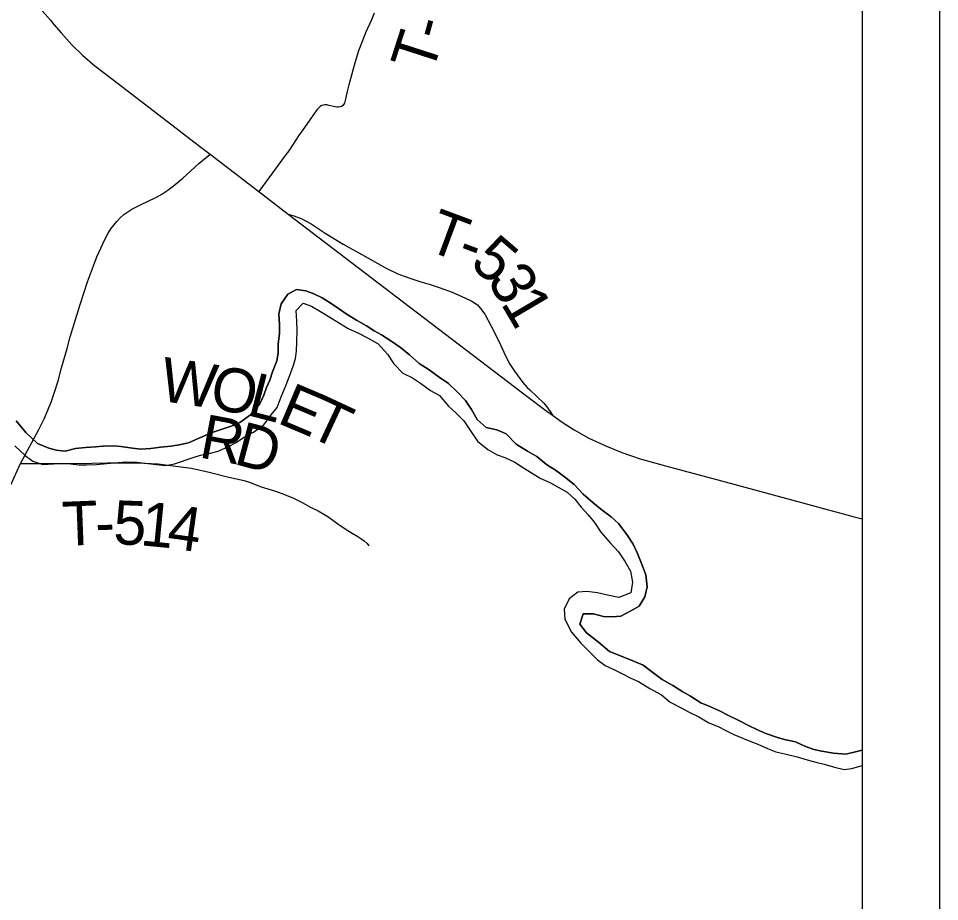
# Model space of a CAD drawing. Extents: x 0 to 34, y 0 to 22.
# Drawn here: x 7.688 to 8.876, y 17.181 to 18.32 of the extents above; entities that cross this region are included whole.
import ezdxf

# ---------------------------------------------------------------- set-up
doc = ezdxf.new("R2010")
doc.units = 0
for name, color, linetype in [('GM_X_County_Road', 7, 'Continuous'), ('GM_X_Major_River', 7, 'Continuous'), ('GM_X_Township_Road', 7, 'Continuous'), ('GM_X_Township_Road_Text', 7, 'Continuous'), ('SH_Data', 7, 'Continuous')]:
    doc.layers.add(name, color=color, linetype=linetype)

msp = doc.modelspace()

# ---------------------------------------------------------------- linework, layer by layer
at = {"layer": 'GM_X_County_Road'}
for points in [[(7.6607, 18.396), (7.6784, 18.3758), (7.6923, 18.3599), (7.7022, 18.3484), (7.7147, 18.334), (7.7289, 18.318), (7.7335, 18.3126)], [(7.7335, 18.3126), (7.7429, 18.3019), (7.7566, 18.2863), (7.7705, 18.273), (7.7864, 18.2592), (7.8093, 18.2414), (7.8799, 18.1872), (7.9195, 18.157), (7.9349, 18.1452), (7.9977, 18.0969), (8.0358, 18.0678), (8.201, 17.942), (8.347, 17.8304), (8.3664, 17.8156), (8.3766, 17.8083), (8.3892, 17.7994), (8.4049, 17.7895), (8.4239, 17.779), (8.4463, 17.7684), (8.4664, 17.7602), (8.4899, 17.7522), (8.5227, 17.7429), (8.5949, 17.7238), (8.7028, 17.6944), (8.7659, 17.6775), (8.7763, 17.6747)], [(7.7504, 17.8946), (7.7546, 17.9096), (7.7672, 17.9512), (7.7769, 17.9806), (7.7843, 18.0011), (7.789, 18.0126), (7.7964, 18.0295), (7.8005, 18.0379), (7.8035, 18.0434), (7.8069, 18.0487), (7.8106, 18.0537), (7.8146, 18.0585), (7.8189, 18.0631), (7.8236, 18.0672), (7.8287, 18.071), (7.8341, 18.0742), (7.8452, 18.0799), (7.8648, 18.0891), (7.8729, 18.0935), (7.8806, 18.0986), (7.8879, 18.1042), (7.8996, 18.1143), (7.9203, 18.133), (7.9298, 18.141), (7.9349, 18.1452)], [(7.6778, 17.7185), (7.6905, 17.7463), (7.7139, 17.7898), (7.7207, 17.8036), (7.7258, 17.8149), (7.7303, 17.8264), (7.7343, 17.8381), (7.7388, 17.8529), (7.7434, 17.8694), (7.7504, 17.8946)]]:
    msp.add_lwpolyline(points, dxfattribs=at)
at = {"layer": 'GM_X_Major_River'}
for p, q in [((8.0353, 17.9645), (8.0267, 17.9523)), ((8.0466, 17.9707), (8.0353, 17.9645)), ((8.0587, 17.9689), (8.0466, 17.9707)), ((8.0689, 17.9649), (8.0587, 17.9689)), ((8.0796, 17.96), (8.0689, 17.9649)), ((8.0267, 17.9523), (8.0238, 17.9394)), ((8.046, 17.9434), (8.055, 17.953)), ((8.055, 17.953), (8.0657, 17.9493)), ((8.0657, 17.9493), (8.0794, 17.9411)), ((8.0898, 17.9533), (8.0796, 17.96)), ((8.102, 17.9451), (8.0898, 17.9533)), ((8.0238, 17.9394), (8.0246, 17.925)), ((8.0469, 17.9298), (8.046, 17.9434)), ((8.0794, 17.9411), (8.0896, 17.9347)), ((8.1119, 17.9383), (8.102, 17.9451)), ((8.1237, 17.9309), (8.1119, 17.9383)), ((8.0474, 17.9173), (8.0469, 17.9298)), ((8.0896, 17.9347), (8.1018, 17.9273)), ((8.1018, 17.9273), (8.1132, 17.9202)), ((8.137, 17.9238), (8.1237, 17.9309)), ((8.0247, 17.9144), (8.023, 17.9)), ((8.0246, 17.925), (8.0247, 17.9144)), ((8.0468, 17.9036), (8.0474, 17.9173)), ((8.1132, 17.9202), (8.1265, 17.9142)), ((8.1265, 17.9142), (8.1391, 17.9079)), ((8.1465, 17.9171), (8.137, 17.9238)), ((8.156, 17.9122), (8.1465, 17.9171)), ((8.0465, 17.8911), (8.0468, 17.9036)), ((8.1391, 17.9079), (8.152, 17.9004)), ((8.1671, 17.9051), (8.156, 17.9122)), ((8.1808, 17.8958), (8.1671, 17.9051)), ((8.023, 17.9), (8.0227, 17.8883)), ((8.0451, 17.8816), (8.0465, 17.8911)), ((8.152, 17.9004), (8.1638, 17.8873)), ((8.1922, 17.8864), (8.1808, 17.8958)), ((8.0209, 17.8784), (8.0157, 17.8643)), ((8.0227, 17.8883), (8.0209, 17.8784)), ((8.0421, 17.8718), (8.0451, 17.8816)), ((8.1638, 17.8873), (8.1719, 17.8745)), ((8.2048, 17.8751), (8.1922, 17.8864)), ((8.0373, 17.8588), (8.0421, 17.8718)), ((8.1719, 17.8745), (8.1837, 17.8628)), ((8.2177, 17.8669), (8.2048, 17.8751)), ((8.2307, 17.8576), (8.2177, 17.8669)), ((8.0157, 17.8643), (8.012, 17.8537)), ((8.0333, 17.8474), (8.0373, 17.8588)), ((8.1837, 17.8628), (8.1963, 17.8565)), ((8.1963, 17.8565), (8.2065, 17.8498)), ((8.2425, 17.8493), (8.2307, 17.8576)), ((8.0076, 17.8442), (8.0042, 17.8343)), ((8.012, 17.8537), (8.0076, 17.8442)), ((8.0266, 17.8322), (8.0333, 17.8474)), ((8.2065, 17.8498), (8.2195, 17.8404)), ((8.2543, 17.8381), (8.2425, 17.8493)), ((8.0042, 17.8343), (7.999, 17.8229)), ((8.0214, 17.8185), (8.0266, 17.8322)), ((8.2195, 17.8404), (8.2309, 17.8337)), ((8.2309, 17.8337), (8.2427, 17.8202)), ((8.2646, 17.8276), (8.2543, 17.8381)), ((7.999, 17.8229), (7.987, 17.8091)), ((8.0139, 17.809), (8.0214, 17.8185)), ((8.2427, 17.8202), (8.2523, 17.8112)), ((8.2723, 17.8159), (8.2646, 17.8276)), ((7.987, 17.8091), (7.9735, 17.7988)), ((8.0042, 17.796), (8.0139, 17.809)), ((8.2523, 17.8112), (8.2622, 17.801)), ((8.2796, 17.8027), (8.2723, 17.8159)), ((7.6974, 17.786), (7.6848, 17.8011)), ((7.9633, 17.7949), (7.9505, 17.7902)), ((7.9735, 17.7988), (7.9633, 17.7949)), ((7.991, 17.7864), (8.0042, 17.796)), ((8.2622, 17.801), (8.2718, 17.7871)), ((8.2914, 17.7926), (8.2796, 17.8027)), ((7.7123, 17.7721), (7.6974, 17.786)), ((7.9365, 17.7855), (7.9218, 17.7793)), ((7.9505, 17.7902), (7.9365, 17.7855)), ((7.9782, 17.7795), (7.991, 17.7864)), ((8.2718, 17.7871), (8.2802, 17.775)), ((8.305, 17.7897), (8.2914, 17.7926)), ((8.3172, 17.7845), (8.305, 17.7897)), ((8.3298, 17.7709), (8.3172, 17.7845)), ((7.7267, 17.7658), (7.7123, 17.7721)), ((7.9071, 17.7728), (7.8951, 17.7704)), ((7.9218, 17.7793), (7.9071, 17.7728)), ((7.9586, 17.7679), (7.9684, 17.7733)), ((7.9684, 17.7733), (7.9782, 17.7795)), ((8.2802, 17.775), (8.2932, 17.7642)), ((8.3446, 17.762), (8.3298, 17.7709)), ((7.6832, 17.7688), (7.6962, 17.7564)), ((7.7362, 17.7633), (7.7267, 17.7658)), ((7.7479, 17.7622), (7.7362, 17.7633)), ((7.7615, 17.7654), (7.7479, 17.7622)), ((7.7744, 17.7666), (7.7615, 17.7654)), ((7.7872, 17.7675), (7.7744, 17.7666)), ((7.7971, 17.7684), (7.7872, 17.7675)), ((7.8099, 17.7689), (7.7971, 17.7684)), ((7.8198, 17.7682), (7.8099, 17.7689)), ((7.8349, 17.7661), (7.8198, 17.7682)), ((7.8455, 17.7646), (7.8349, 17.7661)), ((7.8584, 17.7655), (7.8455, 17.7646)), ((7.8709, 17.7671), (7.8584, 17.7655)), ((7.8841, 17.7684), (7.8709, 17.7671)), ((7.8951, 17.7704), (7.8841, 17.7684)), ((7.9228, 17.757), (7.9356, 17.7594)), ((7.9356, 17.7594), (7.9455, 17.7621)), ((7.9455, 17.7621), (7.9586, 17.7679)), ((8.2932, 17.7642), (8.3053, 17.7575)), ((8.3564, 17.7553), (8.3446, 17.762)), ((7.6962, 17.7564), (7.7064, 17.7493)), ((7.7064, 17.7493), (7.7193, 17.7449)), ((7.8018, 17.746), (7.8162, 17.7473)), ((7.8162, 17.7473), (7.8264, 17.7482)), ((7.8264, 17.7482), (7.8404, 17.7479)), ((7.8404, 17.7479), (7.8514, 17.7465)), ((7.8892, 17.7457), (7.913, 17.7539)), ((7.913, 17.7539), (7.9228, 17.757)), ((8.3053, 17.7575), (8.3152, 17.7538)), ((8.3152, 17.7538), (8.3281, 17.7478)), ((8.3281, 17.7478), (8.3395, 17.7407)), ((8.369, 17.7448), (8.3564, 17.7553)), ((7.7193, 17.7449), (7.7329, 17.7458)), ((7.7329, 17.7458), (7.7435, 17.7466)), ((7.7435, 17.7466), (7.7549, 17.7456)), ((7.7549, 17.7456), (7.7655, 17.7442)), ((7.7655, 17.7442), (7.7753, 17.7443)), ((7.7753, 17.7443), (7.7886, 17.7448)), ((7.7886, 17.7448), (7.8018, 17.746)), ((7.8514, 17.7465), (7.8654, 17.7447)), ((7.8654, 17.7447), (7.8779, 17.7437)), ((7.8779, 17.7437), (7.8892, 17.7457)), ((8.3395, 17.7407), (8.3608, 17.7273)), ((8.3819, 17.7366), (8.369, 17.7448)), ((8.3922, 17.7291), (8.3819, 17.7366)), ((8.3608, 17.7273), (8.3741, 17.7213)), ((8.4048, 17.7189), (8.3922, 17.7291)), ((8.3741, 17.7213), (8.384, 17.7157)), ((8.384, 17.7157), (8.3958, 17.709)), ((8.4163, 17.7065), (8.4048, 17.7189)), ((8.3958, 17.709), (8.4057, 17.7)), ((8.4057, 17.7), (8.4138, 17.6899)), ((8.4292, 17.6953), (8.4163, 17.7065)), ((8.4138, 17.6899), (8.4229, 17.6797)), ((8.441, 17.6859), (8.4292, 17.6953)), ((8.4229, 17.6797), (8.431, 17.6699)), ((8.4525, 17.6773), (8.441, 17.6859)), ((8.462, 17.6687), (8.4525, 17.6773)), ((8.431, 17.6699), (8.439, 17.6575)), ((8.4727, 17.6544), (8.462, 17.6687)), ((8.439, 17.6575), (8.4512, 17.6436)), ((8.4808, 17.642), (8.4727, 17.6544)), ((8.4512, 17.6436), (8.4619, 17.6323)), ((8.4865, 17.6299), (8.4808, 17.642)), ((8.4619, 17.6323), (8.4704, 17.6191)), ((8.4916, 17.617), (8.4865, 17.6299)), ((8.4704, 17.6191), (8.4773, 17.6071)), ((8.4974, 17.6023), (8.4916, 17.617)), ((8.4773, 17.6071), (8.4801, 17.5931)), ((8.4801, 17.5931), (8.4779, 17.5794)), ((8.499, 17.5872), (8.4974, 17.6023)), ((8.4211, 17.5808), (8.4094, 17.5803)), ((8.4348, 17.5794), (8.4211, 17.5808)), ((8.4961, 17.5743), (8.499, 17.5872)), ((8.3985, 17.5715), (8.3918, 17.5582)), ((8.4094, 17.5803), (8.3985, 17.5715)), ((8.4477, 17.5761), (8.4348, 17.5794)), ((8.4624, 17.5732), (8.4477, 17.5761)), ((8.4779, 17.5794), (8.4624, 17.5732)), ((8.4886, 17.5621), (8.4961, 17.5743)), ((8.3918, 17.5582), (8.3927, 17.5453)), ((8.4781, 17.5559), (8.4886, 17.5621)), ((8.3927, 17.5453), (8.4015, 17.5283)), ((8.412, 17.539), (8.4165, 17.5523)), ((8.4165, 17.5523), (8.4297, 17.5521)), ((8.4297, 17.5521), (8.4426, 17.5488)), ((8.4426, 17.5488), (8.4536, 17.5481)), ((8.4536, 17.5481), (8.4649, 17.549)), ((8.4649, 17.549), (8.4781, 17.5559)), ((8.4208, 17.5277), (8.412, 17.539)), ((8.4015, 17.5283), (8.4134, 17.5144)), ((8.4361, 17.5154), (8.4208, 17.5277)), ((8.4134, 17.5144), (8.4237, 17.5039)), ((8.4502, 17.5037), (8.4361, 17.5154)), ((8.4237, 17.5039), (8.4348, 17.493)), ((8.4711, 17.4956), (8.4502, 17.5037)), ((8.4348, 17.493), (8.4447, 17.4855)), ((8.4447, 17.4855), (8.4576, 17.4796)), ((8.4828, 17.4908), (8.4711, 17.4956)), ((8.4938, 17.486), (8.4828, 17.4908)), ((8.5045, 17.4777), (8.4938, 17.486)), ((8.4576, 17.4796), (8.4678, 17.4743)), ((8.4678, 17.4743), (8.4777, 17.4691)), ((8.5182, 17.4676), (8.5045, 17.4777)), ((8.4777, 17.4691), (8.488, 17.4647)), ((8.488, 17.4647), (8.5024, 17.4557)), ((8.5323, 17.4598), (8.5182, 17.4676)), ((8.5024, 17.4557), (8.5176, 17.4475)), ((8.5452, 17.4516), (8.5323, 17.4598)), ((8.5551, 17.446), (8.5452, 17.4516)), ((8.5176, 17.4475), (8.5287, 17.4381)), ((8.5287, 17.4381), (8.5428, 17.4307)), ((8.5684, 17.4374), (8.5551, 17.446)), ((8.5428, 17.4307), (8.553, 17.4255)), ((8.5798, 17.4325), (8.5684, 17.4374)), ((8.5924, 17.427), (8.5798, 17.4325)), ((8.6041, 17.421), (8.5924, 17.427)), ((8.553, 17.4255), (8.5656, 17.4192)), ((8.5656, 17.4192), (8.5785, 17.4117)), ((8.6182, 17.4143), (8.6041, 17.421)), ((8.6307, 17.4076), (8.6182, 17.4143)), ((8.5785, 17.4117), (8.5906, 17.4069)), ((8.5906, 17.4069), (8.6005, 17.4017)), ((8.6406, 17.4028), (8.6307, 17.4076)), ((8.652, 17.3976), (8.6406, 17.4028)), ((8.6005, 17.4017), (8.6108, 17.3964)), ((8.6108, 17.3964), (8.6305, 17.3883)), ((8.6683, 17.392), (8.652, 17.3976)), ((8.6778, 17.3895), (8.6683, 17.392)), ((8.6305, 17.3883), (8.6419, 17.3842)), ((8.6419, 17.3842), (8.6541, 17.3783)), ((8.6903, 17.3869), (8.6778, 17.3895)), ((8.7025, 17.3814), (8.6903, 17.3869)), ((8.7139, 17.3773), (8.7025, 17.3814)), ((8.6541, 17.3783), (8.6651, 17.3742)), ((8.6651, 17.3742), (8.6768, 17.3717)), ((8.6768, 17.3717), (8.6924, 17.3676)), ((8.6924, 17.3676), (8.7053, 17.364)), ((8.7245, 17.3751), (8.7139, 17.3773)), ((8.7393, 17.3726), (8.7245, 17.3751)), ((8.7552, 17.3712), (8.7393, 17.3726)), ((8.7676, 17.374), (8.7552, 17.3712)), ((8.7763, 17.3763), (8.7676, 17.374)), ((8.7053, 17.364), (8.7167, 17.361)), ((8.7167, 17.361), (8.7273, 17.3581)), ((8.7273, 17.3581), (8.7409, 17.3544)), ((8.7629, 17.3527), (8.7763, 17.3566)), ((8.7409, 17.3544), (8.7531, 17.3515)), ((8.7531, 17.3515), (8.7629, 17.3527))]:
    msp.add_line(p, q, dxfattribs=at)
for points in [[(7.6848, 17.8011), (7.6974, 17.786), (7.7123, 17.7721), (7.7267, 17.7658), (7.7362, 17.7633), (7.7479, 17.7622), (7.7615, 17.7654), (7.7744, 17.7666), (7.7872, 17.7675), (7.7971, 17.7684), (7.8099, 17.7689), (7.8198, 17.7682), (7.8349, 17.7661), (7.8455, 17.7646), (7.8584, 17.7655), (7.8709, 17.7671), (7.8841, 17.7684), (7.8951, 17.7704), (7.9071, 17.7728), (7.9218, 17.7793), (7.9365, 17.7855), (7.9505, 17.7902), (7.9633, 17.7949), (7.9735, 17.7988), (7.987, 17.8091), (7.999, 17.8229), (8.0042, 17.8343), (8.0076, 17.8442), (8.012, 17.8537), (8.0157, 17.8643), (8.0209, 17.8784), (8.0227, 17.8883), (8.023, 17.9), (8.0247, 17.9144), (8.0246, 17.925), (8.0238, 17.9394), (8.0267, 17.9523), (8.0353, 17.9645), (8.0466, 17.9707), (8.0587, 17.9689), (8.0689, 17.9649), (8.0796, 17.96), (8.0898, 17.9533), (8.102, 17.9451), (8.1119, 17.9383), (8.1237, 17.9309), (8.137, 17.9238), (8.1465, 17.9171), (8.156, 17.9122), (8.1671, 17.9051), (8.1808, 17.8958), (8.1922, 17.8864), (8.2048, 17.8751)], [(7.6832, 17.7688), (7.6962, 17.7564), (7.7064, 17.7493), (7.7193, 17.7449), (7.7329, 17.7458), (7.7435, 17.7466), (7.7549, 17.7456), (7.7655, 17.7442), (7.7753, 17.7443), (7.7886, 17.7448), (7.8018, 17.746), (7.8162, 17.7473), (7.8264, 17.7482), (7.8404, 17.7479), (7.8514, 17.7465), (7.8654, 17.7447), (7.8779, 17.7437), (7.8892, 17.7457), (7.913, 17.7539), (7.9228, 17.757), (7.9356, 17.7594), (7.9455, 17.7621), (7.9586, 17.7679), (7.9684, 17.7733), (7.9782, 17.7795), (7.991, 17.7864), (8.0042, 17.796), (8.0139, 17.809), (8.0214, 17.8185), (8.0266, 17.8322), (8.0333, 17.8474), (8.0373, 17.8588), (8.0421, 17.8718), (8.0451, 17.8816), (8.0465, 17.8911), (8.0468, 17.9036), (8.0474, 17.9173), (8.0469, 17.9298), (8.046, 17.9434), (8.055, 17.953), (8.0657, 17.9493), (8.0794, 17.9411), (8.0896, 17.9347), (8.1018, 17.9273), (8.1132, 17.9202), (8.1265, 17.9142), (8.1391, 17.9079), (8.152, 17.9004), (8.1638, 17.8873), (8.1719, 17.8745), (8.1837, 17.8628), (8.1963, 17.8565), (8.2065, 17.8498), (8.2195, 17.8404)], [(8.2048, 17.8751), (8.2177, 17.8669), (8.2307, 17.8576), (8.2425, 17.8493), (8.2543, 17.8381), (8.2646, 17.8276), (8.2723, 17.8159), (8.2796, 17.8027), (8.2914, 17.7926), (8.305, 17.7897), (8.3172, 17.7845), (8.3298, 17.7709), (8.3446, 17.762), (8.3564, 17.7553), (8.369, 17.7448), (8.3819, 17.7366), (8.3922, 17.7291), (8.4048, 17.7189), (8.4163, 17.7065), (8.4292, 17.6953), (8.441, 17.6859), (8.4525, 17.6773), (8.462, 17.6687), (8.4727, 17.6544), (8.4808, 17.642), (8.4865, 17.6299), (8.4916, 17.617), (8.4974, 17.6023), (8.499, 17.5872), (8.4961, 17.5743), (8.4886, 17.5621), (8.4781, 17.5559), (8.4649, 17.549), (8.4536, 17.5481), (8.4426, 17.5488), (8.4297, 17.5521), (8.4165, 17.5523), (8.412, 17.539), (8.4208, 17.5277), (8.4361, 17.5154), (8.4502, 17.5037), (8.4711, 17.4956), (8.4828, 17.4908), (8.4938, 17.486), (8.5045, 17.4777), (8.5182, 17.4676), (8.5323, 17.4598), (8.5452, 17.4516), (8.5551, 17.446), (8.5684, 17.4374), (8.5798, 17.4325), (8.5924, 17.427), (8.6041, 17.421), (8.6182, 17.4143), (8.6307, 17.4076), (8.6406, 17.4028), (8.652, 17.3976), (8.6683, 17.392), (8.6778, 17.3895), (8.6903, 17.3869), (8.7025, 17.3814), (8.7139, 17.3773), (8.7245, 17.3751), (8.7393, 17.3726), (8.7552, 17.3712), (8.7676, 17.374), (8.7763, 17.3763)], [(8.2195, 17.8404), (8.2309, 17.8337), (8.2427, 17.8202), (8.2523, 17.8112), (8.2622, 17.801), (8.2718, 17.7871), (8.2802, 17.775), (8.2932, 17.7642), (8.3053, 17.7575), (8.3152, 17.7538), (8.3281, 17.7478), (8.3395, 17.7407), (8.3608, 17.7273), (8.3741, 17.7213), (8.384, 17.7157), (8.3958, 17.709), (8.4057, 17.7), (8.4138, 17.6899), (8.4229, 17.6797), (8.431, 17.6699), (8.439, 17.6575), (8.4512, 17.6436), (8.4619, 17.6323), (8.4704, 17.6191), (8.4773, 17.6071), (8.4801, 17.5931), (8.4779, 17.5794), (8.4624, 17.5732), (8.4477, 17.5761), (8.4348, 17.5794), (8.4211, 17.5808), (8.4094, 17.5803), (8.3985, 17.5715), (8.3918, 17.5582), (8.3927, 17.5453), (8.4015, 17.5283), (8.4134, 17.5144), (8.4237, 17.5039), (8.4348, 17.493), (8.4447, 17.4855), (8.4576, 17.4796), (8.4678, 17.4743), (8.4777, 17.4691), (8.488, 17.4647), (8.5024, 17.4557), (8.5176, 17.4475), (8.5287, 17.4381), (8.5428, 17.4307), (8.553, 17.4255), (8.5656, 17.4192), (8.5785, 17.4117), (8.5906, 17.4069), (8.6005, 17.4017), (8.6108, 17.3964), (8.6305, 17.3883), (8.6419, 17.3842), (8.6541, 17.3783), (8.6651, 17.3742), (8.6768, 17.3717), (8.6924, 17.3676), (8.7053, 17.364), (8.7167, 17.361), (8.7273, 17.3581), (8.7409, 17.3544), (8.7531, 17.3515), (8.7629, 17.3527), (8.7763, 17.3566)]]:
    msp.add_lwpolyline(points, dxfattribs=at)
at = {"layer": 'GM_X_Township_Road'}
for points in [[(8.1467, 18.3271), (8.1432, 18.3187), (8.1355, 18.3016), (8.131, 18.2906), (8.1264, 18.2784), (8.122, 18.2642), (8.1139, 18.2345), (8.1114, 18.2242), (8.1092, 18.2143), (8.1083, 18.2111), (8.1076, 18.2095), (8.1062, 18.2079), (8.1046, 18.2069), (8.1028, 18.2061), (8.1007, 18.2058), (8.0987, 18.2058), (8.0965, 18.2062), (8.0883, 18.2082), (8.0856, 18.2088), (8.0832, 18.2089), (8.0809, 18.2086), (8.0791, 18.2078), (8.0772, 18.2067), (8.075, 18.2047), (8.0729, 18.2022), (8.0567, 18.1795), (8.0492, 18.1688), (8.0414, 18.1568), (8.0365, 18.1496), (8.0319, 18.1434), (8.0026, 18.1035), (7.9977, 18.0969)], [(8.0358, 18.0678), (8.0429, 18.0658), (8.0532, 18.0619), (8.0654, 18.0555), (8.0835, 18.0434), (8.1068, 18.029), (8.1345, 18.0135), (8.1614, 17.9985), (8.1783, 17.9905), (8.1938, 17.9848), (8.2057, 17.9808), (8.2176, 17.9775), (8.2306, 17.9732), (8.2472, 17.9671), (8.2645, 17.9595), (8.2728, 17.9556), (8.2799, 17.9507), (8.2841, 17.9463), (8.2893, 17.9386), (8.2977, 17.9233), (8.3076, 17.9041), (8.3139, 17.8896), (8.321, 17.8755), (8.3277, 17.8654), (8.3387, 17.8505), (8.3442, 17.8443), (8.3475, 17.8412), (8.3655, 17.8239), (8.3709, 17.8173), (8.3748, 17.8117), (8.3766, 17.8083)], [(7.6905, 17.7463), (7.7244, 17.7463), (7.7625, 17.7463), (7.8021, 17.7469), (7.8405, 17.7469), (7.868, 17.7455), (7.8875, 17.7433), (7.9109, 17.7401), (7.9337, 17.735), (7.9593, 17.7285), (7.9788, 17.7242), (7.9878, 17.721), (7.9997, 17.7163), (8.0192, 17.7104), (8.0309, 17.7062), (8.0424, 17.7013), (8.0536, 17.6959), (8.0645, 17.6899), (8.0744, 17.6852), (8.0867, 17.6777), (8.1, 17.6683), (8.1092, 17.662), (8.1183, 17.6563), (8.1254, 17.6521), (8.1308, 17.6485), (8.1339, 17.6464), (8.1375, 17.6429), (8.1398, 17.6399)]]:
    msp.add_lwpolyline(points, dxfattribs=at)
at = {"layer": 'SH_Data'}
for p, q in [((8.8763, 21.1054), (8.8763, 14.1054)), ((8.7763, 21.0054), (8.7763, 14.2054))]:
    msp.add_line(p, q, dxfattribs=at)

# ---------------------------------------------------------------- texts
at = {"layer": 'GM_X_Township_Road_Text'}
for s, rotation, p in [('-', 74.7662, (8.2351, 18.2905)), ('T', 72.0787, (8.2212, 18.2473)), ('T', 339.5905, (8.2116, 18.0224)), ('5', 319.4257, (8.2685, 18.0021)), ('-', 339.2653, (8.2513, 18.0077)), ('3', 300.0907, (8.2916, 17.9834)), ('1', 300.4966, (8.3093, 17.953)), ('W', 351.4164, (7.8681, 17.8275)), ('O', 349.7124, (7.9327, 17.8177)), ('L', 345.4981, (7.9809, 17.809)), ('E', 337.0518, (8.0199, 17.7991)), ('T', 335.0183, (8.0586, 17.7828)), ('R', 349.366, (7.9192, 17.7543)), ('D', 345.0644, (7.964, 17.746)), ('T', 2.2418, (7.745, 17.6398)), ('5', 357.991, (7.8096, 17.642)), ('1', 354.423, (7.8437, 17.6408)), ('4', 352.0009, (7.8779, 17.6375)), ('-', 1.2023, (7.7872, 17.6415))]:
    msp.add_text(s, height=0.0568, rotation=rotation, dxfattribs=at).set_placement(p)

doc.saveas('drawing.dxf')
